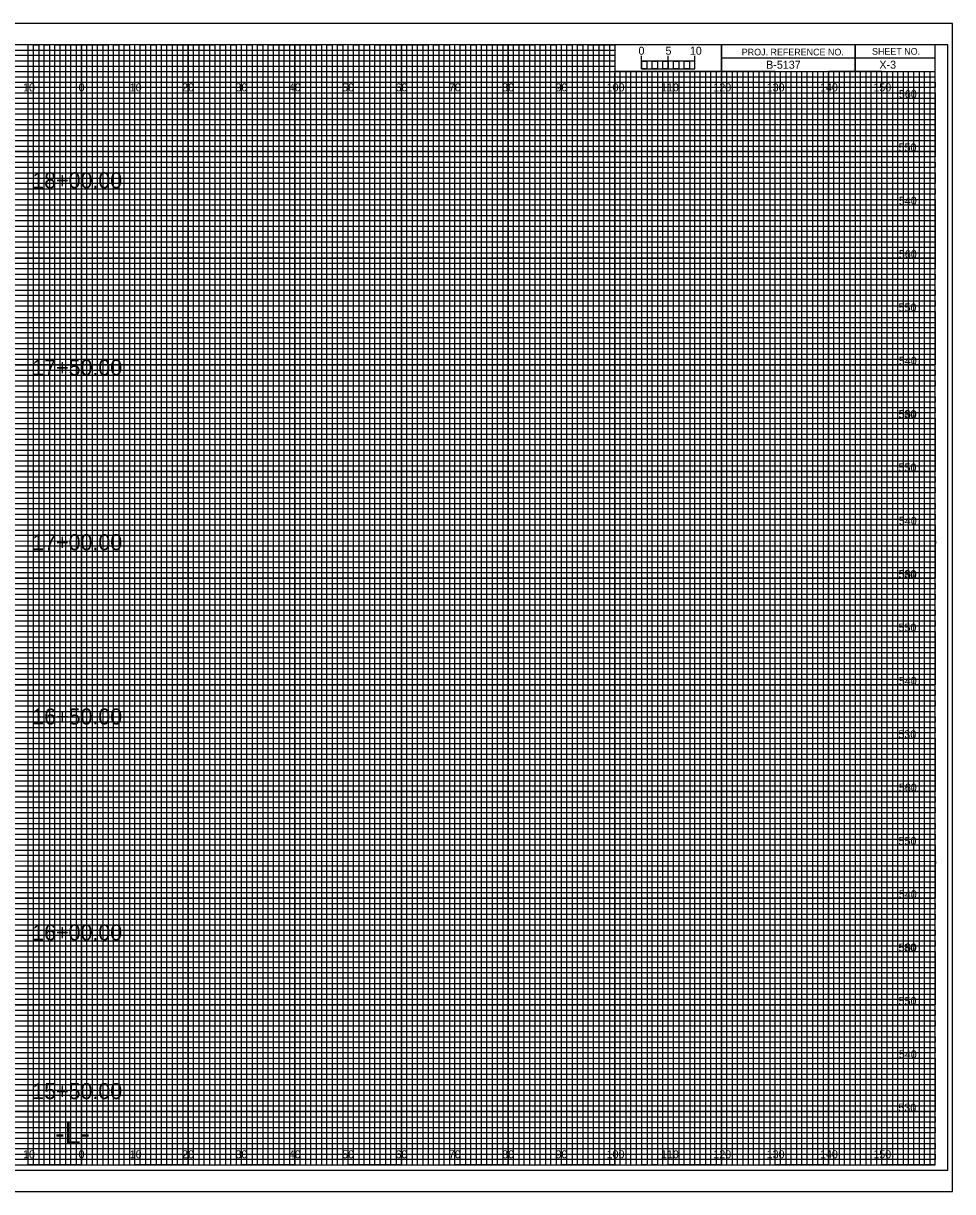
# Model space of a CAD drawing. Extents: x -13 to 323, y 435 to 654.
# Drawn here: x 149.1 to 323.3, y 435 to 654 of the extents above; entities that cross this region are included whole.
import ezdxf

# ---------------------------------------------------------------- set-up
doc = ezdxf.new("R2010")
doc.units = 0
for name, color, linetype in [('Exist Cross Section Cell', 7, 'Continuous'), ('Exist XS Ground Line', 7, 'Continuous'), ('Prop CMT Pvmt Course 1', 7, 'Continuous'), ('Prop CMT Pvmt Course 1 Wedge', 7, 'Continuous'), ('Prop CMT Pvmt Course 2', 7, 'Continuous'), ('Prop CMT Pvmt Course 2 Wedge', 7, 'Continuous'), ('Prop CMT Pvmt Course 3', 7, 'Continuous'), ('Prop CMT Pvmt Surface', 7, 'Continuous'), ('Prop CMT Pvmt Surface Shoulder', 7, 'Continuous'), ('Prop CMT Pvmt Wedge Surface 1', 7, 'Continuous'), ('Prop CMT Pvmt Wedge Surface 2', 7, 'Continuous'), ('Prop CMT Pvmt Wedge Surface 3', 7, 'Continuous'), ('Prop CMT Shld Paved Course 1', 7, 'Continuous'), ('Prop CMT Shld Paved Course 2', 7, 'Continuous'), ('Prop CMT Shld Paved Course 3', 7, 'Continuous'), ('Prop CMT Slope Grass', 7, 'Continuous'), ('Prop CMT Subgrade Earthwork', 7, 'Continuous')]:
    doc.layers.add(name, color=color, linetype=linetype)

msp = doc.modelspace()

# ---------------------------------------------------------------- linework, layer by layer
at = {"layer": 'Exist XS Ground Line'}
for p, q in [((150, 650), (140, 650)), ((150, 440), (150, 650)), ((170, 650), (160, 650)), ((160, 650), (160, 440)), ((170, 440), (170, 650)), ((190, 650), (180, 650)), ((180, 650), (180, 440)), ((190, 440), (190, 650)), ((210, 650), (200, 650)), ((200, 650), (200, 440)), ((210, 440), (210, 650)), ((230, 650), (220, 650)), ((220, 650), (220, 440)), ((230, 440), (230, 650)), ((250, 650), (240, 650)), ((240, 650), (240, 440)), ((250, 440), (250, 650)), ((260, 650), (260, 440)), ((270, 440), (270, 645)), ((290, 645), (280, 645)), ((280, 645), (280, 440)), ((290, 440), (290, 645)), ((310, 645), (300, 645)), ((300, 645), (300, 440)), ((310, 440), (310, 645)), ((160, 440), (150, 440)), ((180, 440), (170, 440)), ((200, 440), (190, 440)), ((220, 440), (210, 440)), ((240, 440), (230, 440)), ((260, 440), (250, 440)), ((280, 440), (270, 440)), ((300, 440), (290, 440)), ((320, 440), (310, 440)), ((320, 440), (320, 440))]:
    msp.add_line(p, q, dxfattribs=at)
for points in [[(0, 640), (320, 640), (320, 630), (0, 630)], [(0, 620), (320, 620), (320, 610), (0, 610)], [(0, 600), (320, 600), (320, 590), (0, 590)], [(0, 580), (320, 580), (320, 570), (0, 570)], [(0, 560), (320, 560), (320, 550), (0, 550)], [(0, 540), (320, 540), (320, 530), (0, 530)], [(0, 520), (320, 520), (320, 510), (0, 510)], [(0, 500), (320, 500), (320, 490), (0, 490)], [(0, 480), (320, 480), (320, 470), (0, 470)], [(0, 460), (320, 460), (320, 450), (0, 450)]]:
    msp.add_lwpolyline(points, dxfattribs=at)
at = {"layer": 'Prop CMT Pvmt Course 2'}
msp.add_lwpolyline([(-13.4, 435), (323.3, 435), (323.3, 654), (-13.4, 654)], close=True, dxfattribs=at)
at = {"layer": 'Prop CMT Pvmt Course 3'}
msp.add_lwpolyline([(-10.8, 439), (322.4, 439), (322.4, 650), (-10.8, 650)], close=True, dxfattribs=at)
at = {"layer": 'Prop CMT Pvmt Surface'}
for p, q in [((150, 440), (150, 650)), ((160, 440), (160, 650)), ((170, 440), (170, 650)), ((180, 440), (180, 650)), ((190, 440), (190, 650)), ((200, 440), (200, 650)), ((210, 440), (210, 650)), ((220, 440), (220, 650)), ((230, 440), (230, 650)), ((240, 440), (240, 650)), ((250, 440), (250, 650)), ((260, 440), (260, 644.69)), ((270, 440), (270, 644.69)), ((280, 440), (280, 644.69)), ((290, 440), (290, 644.69)), ((300, 440), (300, 644.69)), ((310, 440), (310, 644.69)), ((0, 640), (320, 640)), ((0, 630), (320, 630)), ((0, 620), (320, 620)), ((0, 610), (320, 610)), ((0, 600), (320, 600)), ((0, 590), (320, 590)), ((0, 580), (320, 580)), ((0, 570), (320, 570)), ((0, 560), (320, 560)), ((0, 550), (320, 550)), ((0, 540), (320, 540)), ((0, 530), (320, 530)), ((0, 520), (320, 520)), ((0, 510), (320, 510)), ((0, 500), (320, 500)), ((0, 490), (320, 490)), ((0, 480), (320, 480)), ((0, 470), (320, 470)), ((0, 460), (320, 460)), ((0, 450), (320, 450))]:
    msp.add_line(p, q, dxfattribs=at)
at = {"layer": 'Prop CMT Pvmt Wedge Surface 1'}
for p, q in [((323.3, 654), (-13.4, 654)), ((-13.4, 435), (323.3, 435))]:
    msp.add_line(p, q, dxfattribs=at)
at = {"layer": 'Prop CMT Shld Paved Course 1'}
for p, q in [((305, 650), (305, 645)), ((305, 645), (305, 650)), ((280, 647.5), (280, 645)), ((320, 647.49), (280, 647.49)), ((280, 645), (320, 645))]:
    msp.add_line(p, q, dxfattribs=at)
for points in [[(320, 650), (0, 650), (0, 440), (320, 440)], [(280, 650), (260, 650), (260, 645.03), (280, 645.03)], [(320, 650), (280, 650), (280, 645), (320, 645)]]:
    msp.add_lwpolyline(points, close=True, dxfattribs=at)
at = {"layer": 'Prop CMT Shld Paved Course 2'}
for p, q in [((267, 645), (266.01, 645)), ((266.01, 645), (266.01, 440)), ((267, 440), (267, 645)), ((269, 645), (268, 645)), ((268, 645), (268, 440)), ((269, 440), (269, 645)), ((266.01, 440), (265, 440)), ((268, 440), (267, 440))]:
    msp.add_line(p, q, dxfattribs=at)
for points in [[(150, 440), (151, 440), (151, 650), (152, 650), (152, 440)], [(152, 440), (153, 440), (153, 650), (154, 650), (154, 440)], [(155, 440), (156, 440), (156, 650), (157, 650), (157, 440)], [(157, 440), (158, 440), (158, 650), (159, 650), (159, 440)], [(160, 440), (161, 440), (161, 650), (162, 650), (162, 440)], [(162, 440), (163, 440), (163, 650), (164, 650), (164, 440)], [(165, 440), (166, 440), (166, 650), (167, 650), (167, 440)], [(167, 440), (168, 440), (168, 650), (169, 650), (169, 440)], [(170, 440), (171, 440), (171, 650), (172, 650), (172, 440)], [(172, 440), (173, 440), (173, 650), (174, 650), (174, 440)], [(175, 440), (176, 440), (176, 650), (177, 650), (177, 440)], [(177, 440), (178, 440), (178, 650), (179, 650), (179, 440)], [(180, 440), (181, 440), (181, 650), (182, 650), (182, 440)], [(182, 440), (183, 440), (183, 650), (184, 650), (184, 440)], [(185, 440), (186, 440), (186, 650), (187, 650), (187, 440)], [(187, 440), (188, 440), (188, 650), (189, 650), (189, 440)], [(190, 440), (191, 440), (191, 650), (192, 650), (192, 440)], [(192, 440), (193, 440), (193, 650), (194, 650), (194, 440)], [(195, 440), (196, 440), (196, 650), (197, 650), (197, 440)], [(197, 440), (198, 440), (198, 650), (199, 650), (199, 440)], [(200, 440), (201, 440), (201, 650), (202, 650), (202, 440)], [(202, 440), (203, 440), (203, 650), (204, 650), (204, 440)], [(205, 440), (206, 440), (206, 650), (207, 650), (207, 440)], [(207, 440), (208, 440), (208, 650), (209, 650), (209, 440)], [(210, 440), (211, 440), (211, 650), (212, 650), (212, 440)], [(212, 440), (213, 440), (213, 650), (214, 650), (214, 440)], [(215, 440), (216, 440), (216, 650), (217, 650), (217, 440)], [(217, 440), (218, 440), (218, 650), (219, 650), (219, 440)], [(220, 440), (221, 440), (221, 650), (222, 650), (222, 440)], [(222, 440), (223, 440), (223, 650), (224, 650), (224, 440)], [(225, 440), (226, 440), (226, 650), (227, 650), (227, 440)], [(227, 440), (228, 440), (228, 650), (229, 650), (229, 440)], [(230, 440), (231, 440), (231, 650), (232, 650), (232, 440)], [(232, 440), (233, 440), (233, 650), (234, 650), (234, 440)], [(235, 440), (236, 440), (236, 650), (237, 650), (237, 440)], [(237, 440), (238, 440), (238, 650), (239, 650), (239, 440)], [(240, 440), (241, 440), (241, 650), (242, 650), (242, 440)], [(242, 440), (243, 440), (243, 650), (244, 650), (244, 440)], [(245, 440), (246, 440), (246, 650), (247, 650), (247, 440)], [(247, 440), (248, 440), (248, 650), (249, 650), (249, 440)], [(250, 440), (251, 440), (251, 650), (252, 650), (252, 440)], [(252, 440), (253, 440), (253, 650), (254, 650), (254, 440)], [(255, 440), (256, 440), (256, 650), (257, 650), (257, 440)], [(257, 440), (258, 440), (258, 650), (259, 650), (259, 440)], [(260, 440), (261, 440), (261, 645), (262.02, 645), (262.02, 440)], [(262, 440), (263, 440), (263, 645), (263.99, 645), (263.99, 440)], [(270, 440), (270.98, 440), (270.98, 645), (272, 645), (272, 440)], [(272, 440), (273, 440), (273, 645), (274.05, 645), (274.05, 440)], [(275, 440), (276, 440), (276, 645), (277, 645), (277, 440)], [(277, 440), (278, 440), (278, 645), (279, 645), (279, 440)], [(280, 440), (281, 440), (281, 645), (282, 645), (282, 440)], [(282, 440), (283, 440), (283, 645), (284, 645), (284, 440)], [(285, 440), (286, 440), (286, 645), (287, 645), (287, 440)], [(287, 440), (288, 440), (288, 645), (289, 645), (289, 440)], [(290, 440), (291, 440), (291, 645), (292, 645), (292, 440)], [(292, 440), (293, 440), (293, 645), (294, 645), (294, 440)], [(295, 440), (296, 440), (296, 645), (297, 645), (297, 440)], [(297, 440), (298, 440), (298, 645), (299, 645), (299, 440)], [(300, 440), (301, 440), (301, 645), (302, 645), (302, 440)], [(302, 440), (303, 440), (303, 645), (304, 645), (304, 440)], [(305, 440), (306, 440), (306, 645), (307, 645), (307, 440)], [(307, 440), (308, 440), (308, 645), (309, 645), (309, 440)], [(310, 440), (311, 440), (311, 645), (312, 645), (312, 440)], [(312, 440), (313, 440), (313, 645), (314, 645), (314, 440)], [(315, 440), (316, 440), (316, 645), (317, 645), (317, 440)], [(317, 440), (318, 440), (318, 645), (319, 645), (319, 440)]]:
    msp.add_lwpolyline(points, dxfattribs=at)
at = {"layer": 'Prop CMT Shld Paved Course 3'}
for p, q in [((265, 645.49), (265, 647.9)), ((265, 646.9), (265, 647.9)), ((270, 645.49), (270, 647.9)), ((275, 645.49), (275, 647.9)), ((275, 646.9), (275, 647.9))]:
    msp.add_line(p, q, dxfattribs=at)
for points in [[(275, 646.9), (265, 646.9), (265, 645.49), (275, 645.49)], [(265, 646.9), (266, 646.9), (266, 645.49), (265, 645.49)], [(267, 646.9), (268, 646.9), (268, 645.49), (267, 645.49)], [(269, 646.9), (270, 646.9), (270, 645.49), (269, 645.49)], [(271, 646.9), (272, 646.9), (272, 645.49), (271, 645.49)], [(273, 646.9), (274, 646.9), (274, 645.49), (273, 645.49)]]:
    msp.add_lwpolyline(points, close=True, dxfattribs=at)
at = {"layer": 'Prop CMT Slope Grass'}
for p, q in [((0, 649), (260, 649)), ((260, 649), (260, 647.98)), ((260, 647.98), (0, 647.98)), ((0, 647), (260, 647)), ((260, 647), (260, 645.89)), ((260, 645.89), (0, 645.89)), ((0, 644), (320, 644))]:
    msp.add_line(p, q, dxfattribs=at)
for points in [[(0, 643), (270, 643), (320, 643), (320, 642), (0, 642)], [(0, 641), (320, 641), (320, 639), (0, 639)], [(0, 638), (320, 638), (320, 637), (0, 636.98)], [(0, 636), (320, 636), (320, 634), (0, 634)], [(0, 633), (320, 633), (320, 632), (0, 632)], [(0, 631), (320, 631), (320, 629), (0, 629)], [(0, 628), (320, 628), (320, 627), (0, 627)], [(0, 626), (320, 626), (320, 624), (0, 624)], [(0, 623), (320, 623), (320, 622), (0, 622)], [(0, 621), (320, 621), (320, 619), (0, 619)], [(0, 618), (320, 618), (320, 617), (0, 617)], [(0, 616), (320, 616), (320, 613.95), (320, 613), (320, 612), (0, 612)], [(0, 614), (320, 614), (320, 613), (0, 613)], [(0, 611), (320, 611), (320, 609), (0, 609.03)], [(0, 609.03), (320, 609), (320, 608), (0, 608)], [(0, 607), (320, 607), (320, 606), (0, 606)], [(0, 604), (320, 604), (320, 603), (0, 603)], [(0, 602), (320, 602), (320, 601), (0, 601)], [(-0.07, 598.89), (320, 598.89), (320, 597.88), (-0.07, 597.88)], [(0, 597), (320, 597), (320, 596), (0, 596)], [(0, 594), (320, 594), (320, 593), (0, 593)], [(0, 592), (320, 592), (320, 591), (0, 591)], [(0, 589), (320, 589), (320, 588), (0, 588)], [(0, 587), (320, 587), (320, 586), (0, 586)], [(0, 584), (320, 584), (320, 583), (0, 583)], [(0, 582), (320, 582), (320, 581), (0, 581)], [(0, 579), (320, 579), (319.99, 577.98), (0, 578)], [(0, 577), (320, 577), (320, 576), (0, 576)], [(0, 574), (320, 574), (320, 573), (0, 573)], [(0, 572), (320, 572), (320, 571), (0, 571)], [(0, 569), (320, 569), (320, 568), (0, 568)], [(0, 567), (320, 567), (320, 566), (0, 566)], [(0, 564), (320, 564), (320, 563), (0, 563)], [(0, 562), (320, 562), (320, 561), (0, 561)], [(0, 559), (320, 559), (320, 558), (0, 558)], [(0, 556.99), (320.07, 556.91), (320, 556), (0, 556)], [(0, 554), (320, 554), (320, 553), (0, 553)], [(0, 552), (320, 552), (320, 551), (0, 551)], [(0, 549), (320, 549), (320, 548), (0, 548)], [(0, 547), (320, 547), (320, 546), (0, 546)], [(0, 544), (320, 544), (320, 543), (0, 543)], [(0, 542), (320, 542), (320, 541), (0, 541)], [(0, 539), (320, 539), (320, 538), (0, 538)], [(0, 537), (320, 537), (320, 536), (0, 536)], [(0, 534), (320, 534), (320, 533), (0, 533)], [(0, 532), (320, 532), (320, 531), (0, 531)], [(0, 529), (320, 529), (320, 528), (0, 528)], [(0, 527), (320, 527), (320, 526), (0, 526)], [(0, 524), (320, 524), (320, 523), (0, 523)], [(0, 522), (320, 522), (320, 521), (0, 521)], [(0, 519), (320, 519), (319.99, 517.98), (0, 518)], [(0, 517), (320, 517), (320, 516), (0, 516)], [(0, 514), (320, 514), (320, 513), (0, 513)], [(0, 512), (320, 512), (320, 511), (0, 511)], [(0, 509), (320, 509), (320, 508), (0, 508)], [(0, 507), (320, 507), (320, 506), (0, 506)], [(0, 504), (320, 504), (320, 503), (0, 503)], [(0, 502), (320, 502), (320, 501), (0, 501)], [(0, 499), (320, 499), (320, 498), (0, 498)], [(0, 496.99), (320.07, 496.91), (320, 496), (0, 496)], [(0, 494), (320, 494), (320, 493), (0, 493)], [(0, 492), (320, 492), (320, 491), (0, 491)], [(0, 489), (320, 489), (320, 488), (0, 488)], [(0, 487), (320, 487), (320, 486), (0, 486)], [(0, 484), (320, 484), (320, 483), (0, 483)], [(0, 482), (320, 482), (320, 481), (0, 481)], [(0, 479), (320, 479), (320, 478), (0, 478)], [(0, 477), (320, 477), (320, 476), (0, 476)], [(0, 474), (320, 474), (320, 473), (0, 473)], [(0, 472), (320, 472), (320, 471), (0, 471)], [(0, 469), (320, 469), (320, 468), (0, 468)], [(0, 467), (320, 467), (320, 466), (0, 466)], [(0, 464), (320, 464), (320, 463), (0, 463)], [(0, 462), (320, 462), (320, 461), (0, 461)], [(0, 459), (320, 459), (320, 458), (0, 458)], [(0, 457), (320, 457), (320, 456), (0, 456)], [(0, 454), (320, 454), (320, 453), (0, 453)], [(0, 452), (320, 452), (320, 451), (0, 451)], [(0, 449), (320, 449), (320, 448), (0, 448)], [(0, 447), (320, 447), (320, 446), (0, 446)], [(0, 444), (320, 444), (320, 443), (0, 443)], [(0, 442), (320, 442), (320, 441), (0, 441)]]:
    msp.add_lwpolyline(points, dxfattribs=at)
at = {"layer": 'Prop CMT Subgrade Earthwork'}
for points in [[(145, 440), (155, 440), (155, 650), (165, 650), (165, 440), (175, 440), (175, 650), (185, 650), (185, 440), (195, 440), (195, 650), (205, 650), (205, 440), (215, 440), (215, 650), (225, 650), (225, 440), (235, 440), (235, 650), (245, 650), (245, 440), (255, 440), (255, 650), (259.93, 650), (260, 650), (260, 645), (264.99, 645), (264.99, 440), (275, 440), (275, 645), (285, 645), (285, 440), (295, 440), (295, 645), (305, 645), (305, 440), (315, 440), (315, 645)], [(0, 645), (275, 645)], [(0, 625), (320, 625), (320, 635), (0, 635)], [(0, 605), (320, 605), (320, 615), (0, 615)], [(0, 585), (320, 585), (320, 595), (0, 595)], [(0, 565), (320, 565), (320, 575), (0, 575)], [(0, 545), (320, 545), (320, 555), (0, 555)], [(0, 525), (320, 525), (320, 535), (0, 535)], [(0, 505), (320, 505), (320, 515), (0, 515)], [(0, 485), (320, 485), (320, 495), (0, 495)], [(0, 465), (320, 465), (320, 475), (0, 475)], [(0, 445), (320, 445), (320, 455), (0, 455)]]:
    msp.add_lwpolyline(points, dxfattribs=at)

# ---------------------------------------------------------------- texts
at = {"layer": 'Exist Cross Section Cell'}
for s, p in [('10', (149.04, 641.25)), ('0', (159.45, 641.25)), ('0', (159.45, 641.25)), ('10', (169.04, 641.25)), ('20', (178.86, 641.25)), ('30', (188.86, 641.25)), ('40', (198.86, 641.25)), ('50', (208.86, 641.25)), ('60', (218.86, 641.25)), ('70', (228.86, 641.25)), ('80', (238.86, 641.25)), ('90', (248.86, 641.25)), ('100', (258.44, 641.25)), ('110', (268.62, 641.25)), ('120', (278.44, 641.25)), ('130', (288.44, 641.25)), ('140', (298.44, 641.25)), ('150', (308.44, 641.25)), ('10', (149.04, 441.25)), ('0', (159.45, 441.25)), ('0', (159.45, 441.25)), ('10', (169.04, 441.25)), ('20', (178.86, 441.25)), ('30', (188.86, 441.25)), ('40', (198.86, 441.25)), ('50', (208.86, 441.25)), ('60', (218.86, 441.25)), ('70', (228.86, 441.25)), ('80', (238.86, 441.25)), ('90', (248.86, 441.25)), ('100', (258.44, 441.25)), ('110', (268.62, 441.25)), ('120', (278.44, 441.25)), ('130', (288.44, 441.25)), ('140', (298.44, 441.25)), ('150', (308.44, 441.25))]:
    msp.add_text(s, height=1.5, dxfattribs=at).set_placement(p)
at = {"layer": 'Prop CMT Pvmt Course 1'}
msp.add_text('B-5137', height=1.5, dxfattribs=at).set_placement((288.34, 645.5))
at = {"layer": 'Prop CMT Pvmt Course 1 Wedge'}
msp.add_text('-L-', height=4, dxfattribs=at).set_placement((155.06, 444))
at = {"layer": 'Prop CMT Pvmt Course 2 Wedge'}
for s, p in [('5', (269.47, 648.12)), ('10', (274.04, 648.12))]:
    msp.add_text(s, height=1.5, dxfattribs=at).set_placement(p)
at = {"layer": 'Prop CMT Pvmt Surface Shoulder'}
msp.add_text('X-3', height=1.5, dxfattribs=at).set_placement((309.57, 645.5))
at = {"layer": 'Prop CMT Pvmt Wedge Surface 2'}
for s, p in [('560', (313.22, 640)), ('550', (313.17, 630)), ('540', (313.22, 620)), ('560', (313.22, 610)), ('550', (313.17, 600)), ('540', (313.22, 590)), ('530', (313.13, 580)), ('560', (313.22, 580)), ('550', (313.17, 570)), ('540', (313.22, 560)), ('530', (313.13, 550)), ('560', (313.22, 550)), ('550', (313.17, 540)), ('540', (313.22, 530)), ('530', (313.13, 520)), ('560', (313.22, 510)), ('550', (313.17, 500)), ('540', (313.22, 490)), ('530', (313.13, 480)), ('560', (313.22, 480)), ('550', (313.17, 470)), ('540', (313.22, 460)), ('530', (313.13, 450))]:
    msp.add_text(s, height=1.5, dxfattribs=at).set_placement(p)
at = {"layer": 'Prop CMT Pvmt Wedge Surface 3'}
for s, p in [('18+00.00', (150.77, 623.08)), ('17+50.00', (150.77, 588)), ('17+00.00', (150.77, 555.24)), ('16+50.00', (150.77, 522.57)), ('16+00.00', (150.77, 482.1)), ('15+50.00', (150.77, 452.35))]:
    msp.add_text(s, height=3, dxfattribs=at).set_placement(p)
at = {"layer": 'Prop CMT Shld Paved Course 1'}
for s, p in [('PROJ. REFERENCE NO.', (283.77, 647.99)), ('SHEET NO.', (308.19, 648.12))]:
    msp.add_text(s, height=1.25, dxfattribs=at).set_placement(p)
at = {"layer": 'Prop CMT Shld Paved Course 3'}
msp.add_text('0', height=1.5, dxfattribs=at).set_placement((264.41, 648.12))

doc.saveas('drawing.dxf')
